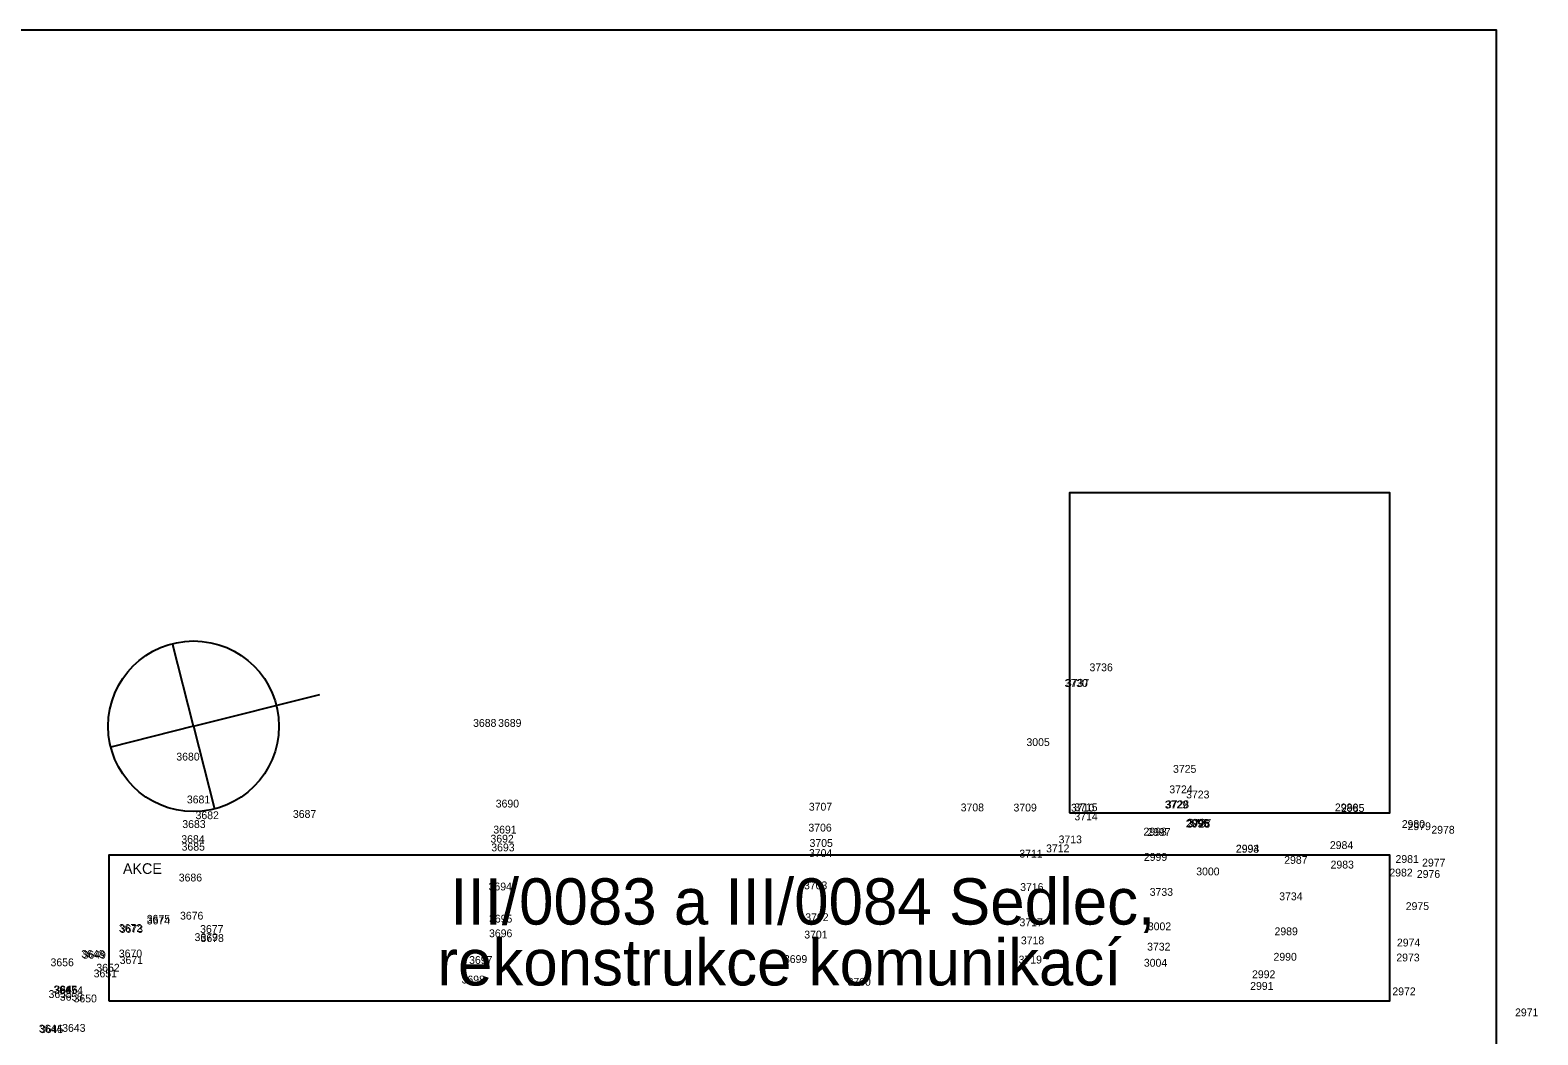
# Model space of a CAD drawing. Extents: x -740053 to -737517, y -1033516 to -1032488.
# Drawn here: x -738987.3 to -738881.3, y -1032577.1 to -1032506.5 of the extents above; entities that cross this region are included whole.
import ezdxf

# ---------------------------------------------------------------- set-up
doc = ezdxf.new("R2010")
doc.units = 0
for name, color, linetype in [('bod-cislo', 7, 'Continuous'), ('Predmety bez rozlišeni', 7, 'Continuous'), ('promika-formát', 7, 'Continuous'), ('promika-rozp', 7, 'Continuous'), ('promika-rozp-poznamky', 7, 'Continuous'), ('promika-rozp-text-firmy', 7, 'Continuous')]:
    doc.layers.add(name, color=color, linetype=linetype)

msp = doc.modelspace()

# ---------------------------------------------------------------- linework, layer by layer
at = {"layer": 'Predmety bez rozlišeni'}
for q in [(-738977.26, -1032549.6), (-738966.91, -1032553.18), (-738981.61, -1032556.88), (-738974.33, -1032561.23)]:
    msp.add_line((-738975.79, -1032555.42), q, dxfattribs=at)
msp.add_circle((-738975.79, -1032555.42), 6, dxfattribs=at)
at = {"layer": 'promika-formát'}
msp.add_lwpolyline([(-738989.25, -1032654.98), (-738884.25, -1032654.98), (-738884.25, -1032506.48), (-738989.25, -1032506.48)], close=True, dxfattribs=at)
at = {"layer": 'promika-rozp'}
msp.add_lwpolyline([(-738981.75, -1032574.73), (-738891.75, -1032574.73), (-738891.75, -1032564.48), (-738981.75, -1032564.48)], close=True, dxfattribs=at)
at = {"layer": 'promika-rozp-poznamky'}
msp.add_lwpolyline([(-738914.25, -1032561.51), (-738891.75, -1032561.51), (-738891.75, -1032539.01), (-738914.25, -1032539.01)], close=True, dxfattribs=at)

# ---------------------------------------------------------------- texts
at = {"layer": 'bod-cislo'}
for s, p in [('3736', (-738912.84, -1032551.55)), ('3730', (-738914.59, -1032552.66)), ('3737', (-738914.5, -1032552.64)), ('3688', (-738956.15, -1032555.46)), ('3689', (-738954.39, -1032555.46)), ('3005', (-738917.27, -1032556.81)), ('3680', (-738977, -1032557.83)), ('3725', (-738906.97, -1032558.69)), ('3681', (-738976.26, -1032560.84)), ('3690', (-738954.56, -1032561.13)), ('3728', (-738907.48, -1032561.18)), ('3724', (-738907.23, -1032560.13)), ('3723', (-738906.05, -1032560.49)), ('3682', (-738975.65, -1032561.95)), ('3687', (-738968.81, -1032561.86)), ('3707', (-738932.56, -1032561.35)), ('3708', (-738921.89, -1032561.4)), ('3709', (-738918.18, -1032561.41)), ('3710', (-738914.14, -1032561.42)), ('3715', (-738913.91, -1032561.39)), ('3714', (-738913.9, -1032562.03)), ('3729', (-738907.55, -1032561.2)), ('2986', (-738895.6, -1032561.4)), ('2985', (-738895.16, -1032561.44)), ('3683', (-738976.58, -1032562.57)), ('3691', (-738954.73, -1032562.96)), ('3706', (-738932.59, -1032562.82)), ('2998', (-738909.05, -1032563.1)), ('2997', (-738908.78, -1032563.13)), ('2996', (-738906.08, -1032562.53)), ('2995', (-738906.03, -1032562.48)), ('3726', (-738906, -1032562.55)), ('3727', (-738905.92, -1032562.48)), ('2980', (-738890.9, -1032562.57)), ('2979', (-738890.49, -1032562.72)), ('2978', (-738888.82, -1032562.97)), ('3684', (-738976.65, -1032563.63)), ('3685', (-738976.63, -1032564.16)), ('3692', (-738954.93, -1032563.6)), ('3693', (-738954.87, -1032564.21)), ('3705', (-738932.51, -1032563.9)), ('3712', (-738915.89, -1032564.28)), ('3713', (-738915.01, -1032563.65)), ('2993', (-738902.56, -1032564.31)), ('2994', (-738902.55, -1032564.29)), ('2984', (-738895.95, -1032564.05)), ('3704', (-738932.55, -1032564.61)), ('3711', (-738917.77, -1032564.65)), ('2999', (-738909.02, -1032564.88)), ('2987', (-738899.16, -1032565.09)), ('2981', (-738891.34, -1032565.03)), ('2977', (-738889.47, -1032565.28)), ('3686', (-738976.83, -1032566.33)), ('3000', (-738905.34, -1032565.9)), ('2983', (-738895.9, -1032565.42)), ('2982', (-738891.77, -1032565.98)), ('2976', (-738889.84, -1032566.08)), ('3694', (-738955.06, -1032566.96)), ('3703', (-738932.9, -1032566.88)), ('3716', (-738917.71, -1032567)), ('3733', (-738908.61, -1032567.34)), ('3734', (-738899.51, -1032567.65)), ('2975', (-738890.62, -1032568.34)), ('3675', (-738979.08, -1032569.23)), ('3674', (-738979.08, -1032569.35)), ('3676', (-738976.74, -1032569.01)), ('3695', (-738955.03, -1032569.22)), ('3702', (-738932.81, -1032569.12)), ('3717', (-738917.76, -1032569.48)), ('3672', (-738981.04, -1032569.88)), ('3673', (-738980.98, -1032569.94)), ('3679', (-738975.72, -1032570.52)), ('3677', (-738975.33, -1032569.95)), ('3678', (-738975.3, -1032570.58)), ('3696', (-738955.03, -1032570.25)), ('3701', (-738932.88, -1032570.34)), ('3002', (-738908.74, -1032569.76)), ('2989', (-738899.84, -1032570.11)), ('3648', (-738983.68, -1032571.7)), ('3649', (-738983.59, -1032571.76)), ('3670', (-738981.04, -1032571.67)), ('3718', (-738917.66, -1032570.75)), ('3732', (-738908.79, -1032571.19)), ('2974', (-738891.24, -1032570.9)), ('3656', (-738985.84, -1032572.29)), ('3652', (-738982.62, -1032572.67)), ('3671', (-738980.98, -1032572.13)), ('3697', (-738956.43, -1032572.13)), ('3699', (-738934.31, -1032572.06)), ('3719', (-738917.82, -1032572.1)), ('3004', (-738909.02, -1032572.32)), ('2990', (-738899.91, -1032571.9)), ('2973', (-738891.28, -1032571.95)), ('3651', (-738982.81, -1032573.07)), ('3698', (-738956.96, -1032573.5)), ('3700', (-738929.84, -1032573.66)), ('2992', (-738901.42, -1032573.13)), ('3655', (-738985.98, -1032574.52)), ('3647', (-738985.63, -1032574.2)), ('3646', (-738985.57, -1032574.21)), ('3654', (-738985.2, -1032574.25)), ('3653', (-738985.19, -1032574.71)), ('3650', (-738984.22, -1032574.83)), ('2991', (-738901.55, -1032573.95)), ('2972', (-738891.56, -1032574.33)), ('2971', (-738882.94, -1032575.81)), ('3644', (-738986.66, -1032576.95)), ('3645', (-738986.59, -1032576.99)), ('3643', (-738985.02, -1032576.9))]:
    msp.add_text(s, height=0.55, dxfattribs=at).set_placement(p)
at = {"layer": 'promika-rozp'}
msp.add_text('AKCE', height=0.75, rotation=360, dxfattribs=at).set_placement((-738980.75, -1032565.8))
at = {"layer": 'promika-rozp-text-firmy'}
for s, p in [('III/0083 a III/0084 Sedlec,', (-738957.75, -1032569.36)), ('rekonstrukce komunikací', (-738958.66, -1032573.64))]:
    msp.add_text(s, height=3.25, rotation=360, dxfattribs=at).set_placement(p)

doc.saveas('drawing.dxf')
